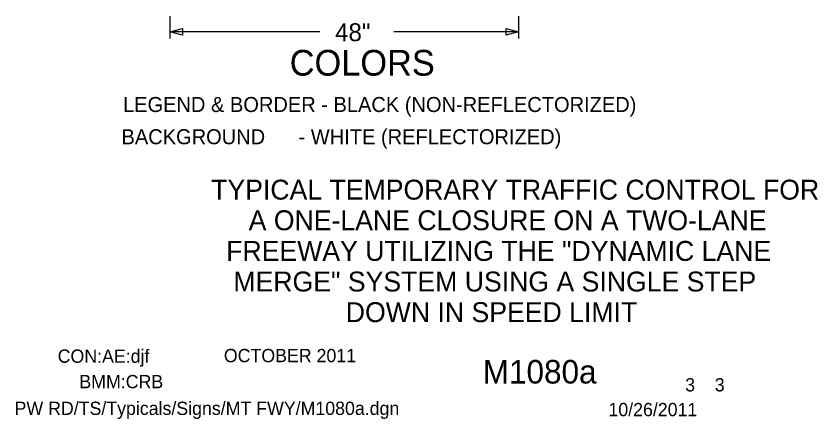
# Model space of a CAD drawing. Extents: x 15277 to 18126, y 1908 to 6555.
# Drawn here: x 17751.9 to 18126.4, y 2176.1 to 2364.2 of the extents above; entities that cross this region are included whole.
import ezdxf

# ---------------------------------------------------------------- set-up
doc = ezdxf.new("R2010")
doc.units = 0
doc.layers.add('BORDER_SIGNAL_WO', color=7, linetype='Continuous')
doc.layers.add('TYPICAL_TEXT_DIMEN_PR', color=7, linetype='Continuous')

msp = doc.modelspace()

# ---------------------------------------------------------------- linework, layer by layer
at = {"layer": 'TYPICAL_TEXT_DIMEN_PR'}
for p, q in [((17823.7, 2364.24), (17823.7, 2353.72)), ((17986.58, 2364.24), (17986.58, 2353.72)), ((17823.7, 2356.82), (17829.57, 2358.39)), ((17893.74, 2356.82), (17823.7, 2356.82)), ((17829.57, 2355.25), (17823.7, 2356.82)), ((17829.57, 2358.39), (17829.57, 2356.82)), ((17829.57, 2356.82), (17829.57, 2355.25)), ((17986.58, 2356.82), (17928.26, 2356.82)), ((17980.71, 2356.82), (17980.71, 2358.39)), ((17980.71, 2358.39), (17986.58, 2356.82)), ((17986.58, 2356.82), (17980.71, 2355.25)), ((17980.71, 2355.25), (17980.71, 2356.82))]:
    msp.add_line(p, q, dxfattribs=at)

# ---------------------------------------------------------------- texts
at = {"layer": 'BORDER_SIGNAL_WO'}
for s, height, p in [('TYPICAL TEMPORARY TRAFFIC CONTROL FOR', 9.3, (17842.98, 2278.54)), ('A ONE-LANE CLOSURE ON A TWO-LANE', 9.3, (17860.5, 2264.24)), ('FREEWAY UTILIZING THE "DYNAMIC LANE', 9.3, (17850, 2249.94)), ('MERGE" SYSTEM USING A SINGLE STEP ', 9.3, (17853.35, 2235.64)), ('DOWN IN SPEED LIMIT', 9.3, (17905.85, 2221.34)), ('CON:AE:djf  ', 6.2, (17771.3, 2202.35)), ('    OCTOBER 2011    ', 6.2, (17839.7, 2202.63)), ('    M1080a   ', 11, (17953.48, 2192.67)), ('BMM:CRB   ', 6.2, (17781.43, 2190.46)), (' 3    3 ', 6.2, (18062.06, 2188.99)), ('PW RD/TS/Typicals/Signs/MT FWY/M1080a.dgn      ', 6.2, (17751.17, 2178)), ('10/26/2011    ', 6.2, (18028.54, 2177.42))]:
    msp.add_text(s, height=height, dxfattribs=at).set_placement(p)
at = {"layer": 'TYPICAL_TEXT_DIMEN_PR'}
for s, height, p in [('48"', 8.4, (17900.88, 2352.48)), ('COLORS', 12, (17879.66, 2336.42)), ('LEGEND & BORDER - BLACK (NON-REFLECTORIZED)', 7, (17801.82, 2319.44)), ('BACKGROUND      - WHITE (REFLECTORIZED)', 7, (17801.1, 2304.39))]:
    msp.add_text(s, height=height, dxfattribs=at).set_placement(p)

doc.saveas('drawing.dxf')
